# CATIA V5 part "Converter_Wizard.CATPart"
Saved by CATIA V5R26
Part number: Converter_Wizard
Bounding box of the stored display mesh (mm): x -73.652 to 68.341, y -110.656 to 85.515, z -5 to 121
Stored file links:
  D:\LinkedIn Learning\NURBS\CATIA\Class Parts\Converter_Wizard.CATPart
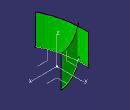
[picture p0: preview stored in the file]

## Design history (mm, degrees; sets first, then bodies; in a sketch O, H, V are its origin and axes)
AxisSystem1: origin (0, 0, 0), X (1, 0, 0), Y (0, 1, 0), Z (0, 0, 1)
Set1
  St3DCurveFeature1 "CATSt3DCurveFeatureName": Order 6, CreationType 1, ClosureMode false, ConstructionPoints ({point type Coord, X 68.341, Y 85.5148, Z 0}; {point type Coord, X 10.9771, Y 80.9115, Z 0}; {point type Coord, X -73.6525, Y 12.5705, Z 0}), SymmetryMode false
  St3DCurveFeature2 "CATSt3DCurveFeatureName": Order 6, CreationType 1, ClosureMode false, ConstructionPoints ({point type Coord, X -61.259, Y 64.2689, Z 0}; {point type Coord, X -63.3836, Y -41.9607, Z 0}; {point type Coord, X -24.7869, Y -110.6558, Z 0}), SymmetryMode false
  Extrude1: Lim1 120, Lim2 0, Element1 St3DCurveFeature2
  Extrude2: Lim1 121, Lim2 5, Element1 St3DCurveFeature1
Body1 (main body)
